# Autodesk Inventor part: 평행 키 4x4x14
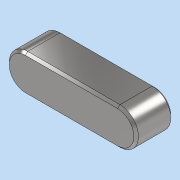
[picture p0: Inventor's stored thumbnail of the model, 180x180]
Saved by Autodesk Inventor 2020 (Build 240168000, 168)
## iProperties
Created: 2024-12
Part Number: 평행 키 4x4x14
Material: 강철, 연강
Description: 키 및 해당 키홈
Document SubType Name: Modeling
Designer: 1강의실14
Density: 7.85 g/cm^3
Appearance: 기본값
Author: jhkim
Sending System: Autodesk Inventor 2025
Preprocessor: ST-DEVELOPER v20
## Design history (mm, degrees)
node "평행 키 4x4x141"
node "솔리드1"
body "Solid1"
